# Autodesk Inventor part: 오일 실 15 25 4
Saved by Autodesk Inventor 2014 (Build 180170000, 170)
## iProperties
Created: 2024-11
Part Number: 오일 실 15 25 4
Material: 일반
Document SubType Name: Modeling
Designer: dg
Density: 1 g/cm^3
Appearance: 기본값
Author: dg
Author: jhkim
Description: 오일 실 - 비스프링, 조립 GA
Creation Date: 2024-10-25
Sending System: Autodesk Inventor 2025
Preprocessor: ST-DEVELOPER v20
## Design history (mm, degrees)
node "오일 실 15 25 41"
body "Solid1"
node "기준1"
